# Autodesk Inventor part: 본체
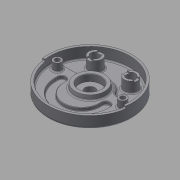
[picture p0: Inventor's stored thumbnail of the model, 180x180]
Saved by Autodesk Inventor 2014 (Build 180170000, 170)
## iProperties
Created: 2015-06
Part Number: 본체
Material: Generic
Document SubType Name: Modeling
Designer: MYHOME
Density: 1 g/cm^3
Appearance: Default
Mass: 395.202 g
Surface Area: 1034.49 cm^2
Volume: 395.202 cm^3
Author: MYHOME
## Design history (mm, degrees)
sketch "스케치1"
  geometry: C1 r 95 at (0, 0); 1 further point
  constraints: 1 centre point, 1 coincident
  dimensions: "d0" = 190 diameter of C1
extrude "돌출1" new body sketch "스케치1" distance "d1" = 32; taper "d2" = 0 deg
sketch "스케치2"
  geometry: L1 (-88.566, 16)-(88.566, 16); C1 r 95 at (0, 0) reference; A1 r 90 centre (0, 0) between (-90, 0) and (88.566, 16); A2 r 42 centre (0, 0) between (38.833, 16) and (-38.833, 16); 2 further points
  constraints: 5 point on circle, 2 centre point, 2 coincident, 2 end point, 2 horizontal alignment, 2 point on line, 1 midpoint, 1 vertical alignment
  dimensions: "d3" = 180 diameter of A1; "d4" = 84 diameter of A2; "d6" = 16 distance from line of L1 C1.centre
extrude "돌출2" cut sketch "스케치2" distance "d7" = 25; taper "d8" = 0 deg
fillet "모깎기1" dims "d9" = 10
fillet "모깎기2" dims "d10" = 10
sketch "스케치3"
  geometry: L1 (-45.033, 16)-(-75.657, 16) reference; L2 (75.657, 16)-(45.033, 16) reference; C1 r 95 at (0, 0) reference; C2 r 90 at (0, 0); A1 r 42 centre (0, 0) between (36.373, 21) and (-36.373, 21) reference; A2 r 10 centre (-45.033, 26) between (-45.033, 16) and (-36.373, 21) reference; A3 r 10 centre (-75.657, 26) between (-85.114, 29.25) and (-75.657, 16) reference; A4 r 90 centre (0, 0) between (85.114, 29.25) and (-85.114, 29.25) reference; A5 r 10 centre (75.657, 26) between (75.657, 16) and (85.114, 29.25) reference; A6 r 10 centre (45.033, 26) between (36.373, 21) and (45.033, 16) reference
  constraints: 1 centre point, 1 coincident
  dimensions: "d11" = 180 diameter of C2
extrude "돌출3" cut sketch "스케치3" distance "d12" = 18; taper "d13" = 0 deg
sketch "스케치4"
  geometry: C1 r 35 at (0, 0); A1 r 42 centre (0, 0) between (36.373, 21) and (-36.373, 21) reference
  constraints: 1 centre point, 1 coincident
  dimensions: "d14" = 70 diameter of C1
extrude "돌출4" join sketch "스케치4" distance "d15" = 10; taper "d16" = -10 deg
sketch "스케치5"
  geometry: L1 (-75.657, 16)-(-45.033, 16) reference; L2 (-59, -19)-(-59, -14); L3 (-41, -19)-(-41, -14); L4 (41, -19)-(41, -14); L5 (59, -19)-(59, -14); C1 r 35 at (0, 0) reference; A1 r 59 centre (0, -19) between (-59, -19) and (59, -19); A2 r 41 centre (0, -19) between (-41, -19) and (41, -19); A3 r 9 centre (-50, -14) between (-41, -14) and (-59, -14); A4 r 9 centre (50, -14) between (59, -14) and (41, -14); 1 further point
  constraints: 8 end point, 8 point on circle, 4 centre point, 4 tangent, 3 parallel, 1 coincident, 1 perpendicular, 1 vertical alignment
  dimensions: "d19" = 19 distance of C1.centre A1.centre; "d20" = 59 radius of A1; "d21" = 41 radius of A2; "d22" = 5 distance of L2.start L2.end; "d23" = 5 distance of L3.start L3.end; "d24" = 5 distance of L4.start L4.end; "d25" = 5 distance of L5.start L5.end; "d26" = 9 radius of A3; "d27" = 9 radius of A4
extrude "돌출5" cut sketch "스케치5" distance "d28" = 7; taper "d29" = 0 deg
chamfer "모따기1" distance "d34" = 1; stored, may be unused: second distance "d35" = 2, angle "d36" = 45 deg
sketch "스케치7"
  geometry: C1 r 95 at (0, 0) reference; C2 r 26 at (0, 0)
  constraints: 1 centre point, 1 coincident
  dimensions: "d37" = 52 diameter of C2
extrude "돌출7" join sketch "스케치7" distance "d38" = 12; taper "d39" = -15 deg
sketch "스케치8"
  geometry: C1 r 33.237 at (0, 0) reference; C2 r 25 at (0, 0)
  constraints: 1 centre point, 1 coincident
  dimensions: "d40" = 50 diameter of C2
extrude "돌출8" cut sketch "스케치8" distance "d41" = 15; taper "d42" = 0 deg
sketch "스케치9"
  geometry: C1 r 22.785 at (0, 0) reference; C2 r 11.5 at (0, 0)
  constraints: 1 centre point, 1 coincident
  dimensions: "d43" = 23 diameter of C2
extrude "돌출9" cut sketch "스케치9" distance "d44" = 21; taper "d45" = 0 deg
chamfer "모따기2" distance "d46" = 1; stored, may be unused: second distance "d47" = 2, angle "d48" = 45 deg
fillet "모깎기3" dims "d49" = 3
fillet "모깎기4" dims "d50" = 3
sketch "스케치10"
  geometry: C1 r 9 at (-74, 0); C2 r 9 at (74, 0); A1 r 87 centre (0, 0) between (-85.273, 17.251) and (85.273, 17.251) reference
  constraints: 2 centre point, 2 horizontal alignment
  dimensions: "d51" = 18 diameter of C1; "d52" = 18 diameter of C2; "d53" = 148 distance of C2.centre C1.centre; "d54" = 74 distance of C2.centre A1.centre (= 0.5 x d53)
extrude "돌출10" join sketch "스케치10" stored distance "d55" = 11; taper "d56" = 0 deg
fillet "모깎기5" dims "d57" = 3
sketch "스케치11"
  geometry: C1 r 9 at (0, 0) reference; C2 r 5.5 at (0, 0); C3 r 9 at (148, 0) reference; C4 r 5.5 at (148, 0); 1 further point
  constraints: 2 centre point, 2 coincident
  dimensions: "d58" = 11 diameter of C2; "d59" = 11 diameter of C4
extrude "돌출11" cut sketch "스케치11" distance "d60" = 21; taper "d61" = 0 deg
sketch "스케치12"
  geometry: C1 r 5.5 at (-74, 0) reference; C2 r 5.5 at (74, 0) reference; C3 r 9 at (-74, 0); C4 r 9 at (74, 0)
  constraints: 2 centre point, 2 coincident
  dimensions: "d62" = 18 diameter of C3; "d63" = 18 diameter of C4
extrude "돌출12" cut sketch "스케치12" distance "d64" = 11; taper "d65" = 0 deg
fillet "모깎기6" dims "d66" = 5
fillet "모깎기7" dims "d67" = 0.3
sketch "스케치13"
  geometry: C1 r 15 at (-40, 52); C2 r 15 at (40, 52); A1 r 87 centre (0, 0) between (82.277, 28.275) and (-82.277, 28.275) reference
  constraints: 2 centre point
  dimensions: "d68" = 30 diameter of C1; "d69" = 30 diameter of C2; "d70" = 52 vertical distance of C2.centre A1.centre; "d71" = 52 vertical distance of C1.centre A1.centre; "d72" = 80 distance of C2.centre C1.centre; "d73" = 40 horizontal distance of C2.centre A1.centre
extrude "돌출13" join sketch "스케치13" stored distance "d74" = 11; taper "d75" = 0 deg
fillet "모깎기8" dims "d76" = 3
sketch "스케치14"
  geometry: L1 (-6, -15)-(6, -15); L2 (6, -15)-(6, 15); L3 (6, 15)-(-6, 15); L4 (-6, 15)-(-6, -15); L5 (-6, -15)-(6, 15); L6 (6, -15)-(-6, 15); L7 (95, -6)-(65, -6); L8 (65, -6)-(65, 6); L9 (65, 6)-(95, 6); L10 (95, 6)-(95, -6); L11 (95, -6)-(65, 6); L12 (65, -6)-(95, 6); C1 r 15 at (0, 0) reference; C2 r 15 at (80, 0) reference; 1 further point
  constraints: 24 end point, 4 midpoint, 4 parallel, 2 horizontal, 2 perpendicular
  dimensions: "d77" = 12 distance of L3.end L2.end; "d78" = 30 distance of L2.end L1.end; "d79" = 30 distance of L8.end L9.end; "d80" = 12 distance of L7.end L8.end
extrude "돌출14" cut sketch "스케치14" distance "d81" = 3; taper "d82" = 0 deg
sketch "스케치15"
  geometry: L1 (66.252, 6)-(93.748, 6) reference; C1 r 10 at (0, 0); C2 r 10 at (80, 0); A1 r 15 centre (0, 0) between (-6, 13.748) and (-6, -13.748) reference; A2 r 15 centre (80, 0) between (93.748, 6) and (66.252, 6) reference; 1 further point
  constraints: 2 centre point, 2 coincident
  dimensions: "d83" = 20 diameter of C1; "d84" = 20 diameter of C2
extrude "돌출15" cut sketch "스케치15" distance "d85" = 32; taper "d86" = 0 deg
fillet "모깎기9" dims "d87" = 3
sketch "스케치16"
  geometry: C1 r 90 at (0, 0) reference; C2 r 68 at (0, 0)
  constraints: 1 centre point, 1 coincident, 1 other
  dimensions: "d88" = 136 diameter of C2
feature "엠보싱1" sketch "스케치16" dims "d0" = 190, "d89" = 0.5, "d90" = 0
sketch "스케치17"
  geometry: L1 (0, 0)-(-95, 0); L2 (-94.075, -13.221)-(0, 0); L3 (0, 0)-(95, 0); L4 (0, 0)-(94.075, -13.221); A1 r 95 centre (0, 0) between (-95, 0) and (-94.075, -13.221) reference; A2 r 90 centre (0, 0) between (89.124, -12.526) and (-89.124, -12.526) reference
  constraints: 8 end point, 6 point on circle, 2 point on line, 1 collinear, 1 horizontal
  dimensions: "d92" = 8 deg angle of L1 L2; "d93" = 8 deg angle of L3 L4
extrude "돌출16" cut sketch "스케치17" distance "d94" = 5; taper "d95" = 0 deg
fillet "모깎기11" dims "d96" = 3
fillet "모깎기12" dims "d97" = 1
sketch "스케치18"
  geometry: 1 further point
sketch "스케치19"
  geometry: 1 further point
node "솔리드1"
node "투영된 루프1"
node "투영된 루프2"
other parameters: "d18" = 118
